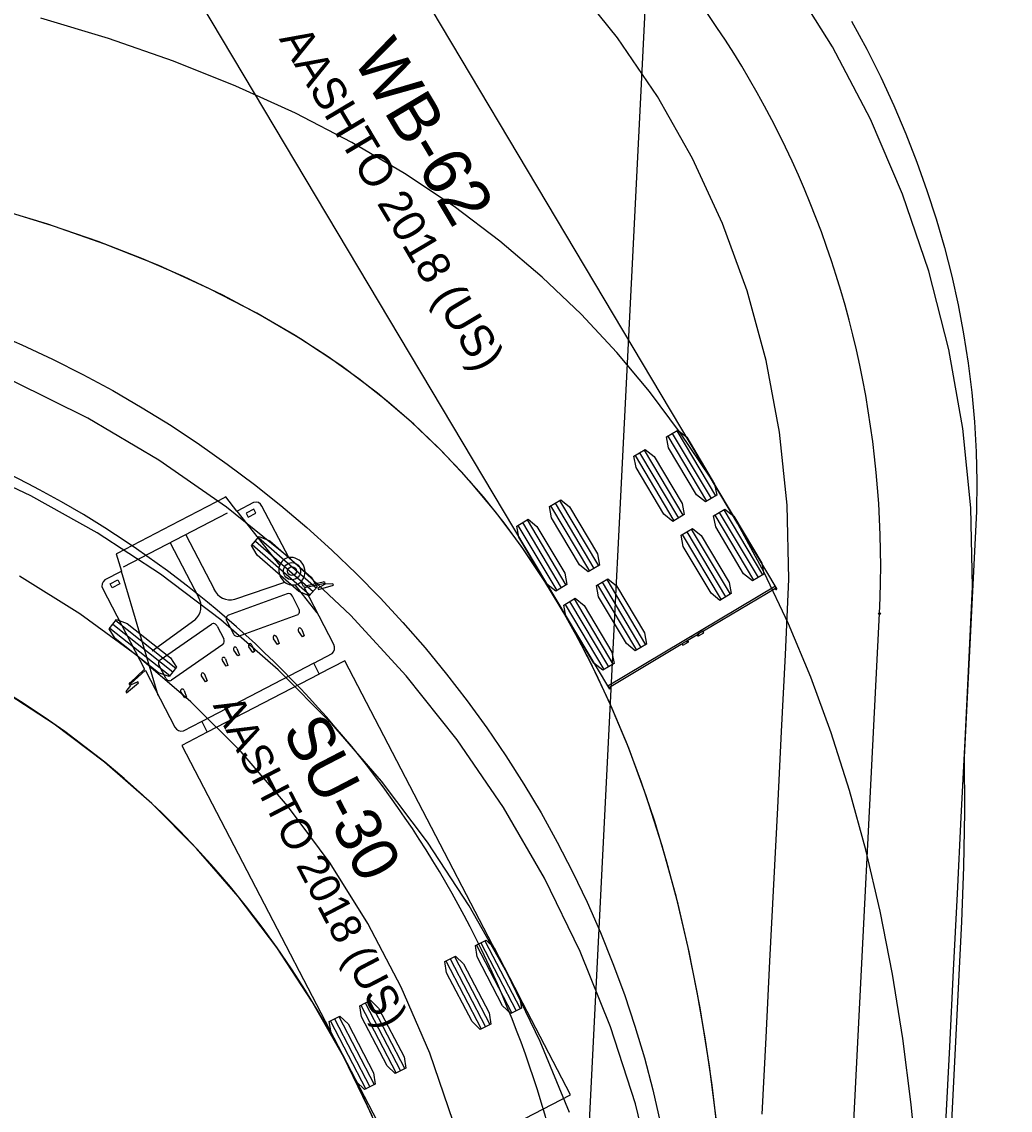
# Model space of a CAD drawing. Extents: x 260275 to 261282, y 610916 to 614143.
# Drawn here: x 261043.72 to 261086.74, y 612552.98 to 612600.34 of the extents above; entities that cross this region are included whole.
import ezdxf

# ---------------------------------------------------------------- set-up
doc = ezdxf.new("R2010")
doc.units = 0
doc.layers.add('GE_X_Alignment', color=7, linetype='Continuous')
doc.layers.add('TopoDOT_Transients', color=7, linetype='Continuous')

msp = doc.modelspace()

# ---------------------------------------------------------------- linework, layer by layer
at = {"layer": 'GE_X_Alignment'}
msp.add_line((260986.249, 610915.954), (261148.276, 614142.838), dxfattribs=at)
at = {"layer": 'TopoDOT_Transients'}
for p, q in [((261072.027, 612582.431), (261073.717, 612579.596)), ((261072.224, 612582.548), (261073.914, 612579.713)), ((261071.831, 612582.313), (261073.52, 612579.478)), ((261070.61, 612581.586), (261072.299, 612578.751)), ((261070.807, 612581.703), (261072.496, 612578.868)), ((261070.413, 612581.469), (261072.102, 612578.634)), ((261053.823, 612579.132), (261053.487, 612578.957)), ((261053.913, 612578.96), (261053.823, 612579.132)), ((261055.339, 612577.03), (261054.175, 612579.268)), ((261066.734, 612579.276), (261068.423, 612576.441)), ((261066.93, 612579.393), (261068.62, 612576.558)), ((261067.127, 612579.51), (261068.817, 612576.676)), ((261074.272, 612579.112), (261075.961, 612576.277)), ((261052.665, 612578.963), (261048.136, 612576.609)), ((261054.95, 612576.698), (261053.091, 612579.046)), ((261053.487, 612578.957), (261053.577, 612578.785)), ((261053.577, 612578.785), (261053.913, 612578.96)), ((261065.71, 612578.666), (261067.399, 612575.831)), ((261073.878, 612578.877), (261075.568, 612576.042)), ((261074.075, 612578.994), (261075.764, 612576.16)), ((261065.316, 612578.431), (261067.006, 612575.596)), ((261065.513, 612578.549), (261067.202, 612575.714)), ((261072.855, 612578.267), (261074.544, 612575.432)), ((261050.858, 612578.024), (261052.089, 612575.657)), ((261053.888, 612577.749), (261056.401, 612575.559)), ((261054.025, 612577.907), (261056.538, 612575.716)), ((261072.461, 612578.032), (261074.15, 612575.198)), ((261072.658, 612578.15), (261074.347, 612575.315)), ((261050.179, 612577.671), (261051.409, 612575.304)), ((261053.751, 612577.592), (261056.264, 612575.402)), ((261049.664, 612571.035), (261048.059, 612576.431)), ((261047.568, 612575.881), (261047.904, 612576.056)), ((261047.658, 612575.709), (261047.568, 612575.881)), ((261047.994, 612575.883), (261047.658, 612575.709)), ((261047.904, 612576.056), (261047.994, 612575.883)), ((261052.992, 612575.217), (261055.171, 612575.958)), ((261056.585, 612574.632), (261055.624, 612575.847)), ((261068.781, 612575.84), (261070.471, 612573.005)), ((261068.978, 612575.957), (261070.667, 612573.122)), ((261069.175, 612576.074), (261070.864, 612573.24)), ((261055.27, 612575.456), (261052.718, 612574.526)), ((261055.783, 612574.8), (261055.498, 612575.347)), ((261076.521, 612575.785), (261069.219, 612571.434)), ((261067.364, 612574.995), (261069.053, 612572.16)), ((261067.561, 612575.112), (261069.25, 612572.278)), ((261067.758, 612575.23), (261069.447, 612572.395)), ((261053.162, 612573.606), (261055.714, 612574.537)), ((261059.045, 612136.423), (261081.046, 612574.591)), ((261047.556, 612573.964), (261050.17, 612571.895)), ((261047.686, 612574.127), (261050.299, 612572.058)), ((261047.815, 612574.29), (261050.429, 612572.221)), ((261051.25, 612574.311), (261049.4, 612572.961)), ((261049.745, 612572.584), (261051.973, 612574.139)), ((261052.228, 612574.043), (261052.512, 612573.496)), ((261052.65, 612574.263), (261052.934, 612573.716)), ((261055.906, 612573.9), (261056.012, 612573.618)), ((261054.851, 612573.251), (261054.68, 612573.501)), ((261054.817, 612573.572), (261054.924, 612573.289)), ((261055.939, 612573.58), (261055.769, 612573.829)), ((261056.012, 612573.618), (261055.939, 612573.58)), ((261072.683, 612573.416), (261073.133, 612573.684)), ((261072.906, 612573.549), (261072.87, 612573.61)), ((261073.363, 612573.821), (261073.134, 612573.685)), ((261052.471, 612573.247), (261050.242, 612571.693)), ((261053.122, 612572.748), (261052.952, 612572.998)), ((261053.089, 612573.069), (261053.196, 612572.786)), ((261053.775, 612572.898), (261053.605, 612573.147)), ((261053.742, 612573.218), (261053.848, 612572.936)), ((261054.924, 612573.289), (261054.851, 612573.251)), ((261072.678, 612573.413), (261072.45, 612573.277)), ((261052.625, 612572.3), (261052.455, 612572.549)), ((261052.592, 612572.62), (261052.698, 612572.338)), ((261053.196, 612572.786), (261053.122, 612572.748)), ((261053.848, 612572.936), (261053.775, 612572.898)), ((261049.988, 612571.788), (261049.703, 612572.335)), ((261056.426, 612572.436), (261051.553, 612569.903)), ((261052.698, 612572.338), (261052.625, 612572.3)), ((261051.718, 612571.623), (261051.54, 612571.884)), ((261051.677, 612571.955), (261051.791, 612571.661)), ((261051.791, 612571.661), (261051.718, 612571.623)), ((261056.671, 612571.964), (261051.798, 612569.431)), ((261050.823, 612570.921), (261050.653, 612571.17)), ((261050.79, 612571.242), (261050.896, 612570.959)), ((261050.896, 612570.959), (261050.823, 612570.921)), ((261063.51, 612560.169), (261065.048, 612557.211)), ((261063.695, 612560.265), (261065.233, 612557.307)), ((261063.88, 612560.361), (261065.417, 612557.403)), ((261062.18, 612559.477), (261063.717, 612556.519)), ((261062.364, 612559.573), (261063.902, 612556.615)), ((261062.549, 612559.669), (261064.086, 612556.712)), ((261058.482, 612557.556), (261060.02, 612554.598)), ((261058.667, 612557.652), (261060.205, 612554.694)), ((261058.852, 612557.748), (261060.389, 612554.79)), ((261057.151, 612556.864), (261058.689, 612553.906)), ((261057.336, 612556.96), (261058.874, 612554.002)), ((261057.521, 612557.056), (261059.058, 612554.098))]:
    msp.add_line(p, q, dxfattribs=at)
for points in [[(261076.538, 612575.713), (261076.557, 612575.725), (261052.021, 612616.898), (261048.37, 612614.722), (261044.72, 612612.547), (261069.255, 612571.373), (261069.275, 612571.385)], [(261075.948, 612552.816), (261076.115, 612556.146), (261076.282, 612559.475), (261076.449, 612562.805), (261076.616, 612566.134), (261076.784, 612569.464), (261076.951, 612572.793), (261077.096, 612576.091), (261077.025, 612579.315), (261076.696, 612582.49), (261076.113, 612585.6), (261075.282, 612588.632), (261074.21, 612591.568), (261072.907, 612594.394), (261071.382, 612597.093), (261069.647, 612599.651), (261067.713, 612602.053)], [(261083.938, 612552.415), (261084.105, 612555.744), (261084.272, 612559.074), (261084.439, 612562.404), (261084.606, 612565.733), (261084.773, 612569.063), (261084.941, 612572.392), (261085.088, 612575.755), (261085.017, 612579.193), (261084.677, 612582.646), (261084.068, 612586.089), (261083.192, 612589.496), (261082.051, 612592.842), (261080.651, 612596.105), (261078.999, 612599.26), (261077.103, 612602.288)], [(261082.717, 612550.298), (261082.431, 612553.229), (261082.066, 612556.101), (261081.616, 612558.908), (261081.08, 612561.647), (261080.456, 612564.313), (261079.744, 612566.9), (261078.943, 612569.405), (261078.054, 612571.821), (261077.081, 612574.146), (261076.024, 612576.375), (261074.887, 612578.504), (261073.674, 612580.529), (261072.39, 612582.446), (261071.038, 612584.254), (261069.616, 612585.959), (261068.065, 612587.621), (261066.372, 612589.238), (261064.53, 612590.802), (261062.534, 612592.304), (261060.384, 612593.737), (261058.08, 612595.093), (261055.63, 612596.365), (261053.041, 612597.545), (261050.324, 612598.629), (261047.492, 612599.613), (261044.559, 612600.497)], [(261079.835, 612600.368), (261080.491, 612599.152), (261081.102, 612597.929), (261081.668, 612596.702), (261082.192, 612595.472), (261082.673, 612594.239), (261083.112, 612593.003), (261083.511, 612591.764), (261083.869, 612590.522), (261084.187, 612589.276), (261084.466, 612588.024), (261084.706, 612586.763), (261084.907, 612585.493), (261085.066, 612584.215), (261085.183, 612582.93), (261085.256, 612581.638), (261085.285, 612580.339), (261085.268, 612579.036), (261084.738, 612568.348), (261084.74, 612565.962), (261084.698, 612563.575), (261084.616, 612561.187), (261082.631, 612521.243), (261060.03, 612071.291)], [(261073.983, 612552.295), (261073.65, 612554.907), (261073.245, 612557.436), (261072.766, 612559.879), (261072.215, 612562.233), (261071.591, 612564.494), (261070.898, 612566.661), (261070.136, 612568.73), (261069.31, 612570.7), (261068.423, 612572.569), (261067.48, 612574.335), (261066.484, 612575.996), (261065.44, 612577.552), (261064.355, 612579.001), (261063.225, 612580.354), (261062.002, 612581.663), (261060.666, 612582.938), (261059.203, 612584.177), (261057.601, 612585.382), (261055.851, 612586.547), (261053.949, 612587.665), (261051.893, 612588.73), (261049.688, 612589.734), (261047.34, 612590.67), (261044.857, 612591.532), (261042.252, 612592.316)], [(261074.018, 612551.977), (261073.764, 612554.08), (261073.465, 612556.13), (261073.118, 612558.126), (261072.725, 612560.067), (261072.286, 612561.95), (261071.8, 612563.775), (261071.269, 612565.54), (261070.693, 612567.244), (261070.075, 612568.885), (261069.416, 612570.462), (261068.717, 612571.975), (261067.981, 612573.422), (261067.21, 612574.803), (261066.407, 612576.117), (261065.573, 612577.363), (261064.71, 612578.545), (261063.81, 612579.672), (261062.865, 612580.756), (261061.861, 612581.805), (261060.787, 612582.828), (261059.631, 612583.83), (261058.389, 612584.808), (261057.055, 612585.761), (261055.626, 612586.686), (261054.101, 612587.581), (261052.478, 612588.441), (261050.76, 612589.262), (261048.949, 612590.042), (261047.049, 612590.777), (261045.064, 612591.464), (261043, 612592.102)], [(261042.375, 612586.868), (261043.725, 612586.285), (261045.06, 612585.662), (261046.379, 612584.998), (261047.68, 612584.295), (261048.961, 612583.552), (261050.22, 612582.771), (261051.454, 612581.953), (261052.663, 612581.1), (261053.845, 612580.212), (261054.998, 612579.29), (261056.122, 612578.336), (261057.217, 612577.348), (261058.281, 612576.33), (261059.313, 612575.281), (261060.312, 612574.202), (261061.278, 612573.096), (261062.209, 612571.962), (261063.105, 612570.801), (261063.965, 612569.616), (261064.788, 612568.406), (261065.573, 612567.174), (261066.319, 612565.92), (261067.026, 612564.646), (261067.693, 612563.353), (261068.32, 612562.041), (261068.905, 612560.713), (261069.447, 612559.37), (261069.947, 612558.013), (261070.403, 612556.642), (261070.815, 612555.261), (261071.183, 612553.869), (261071.505, 612552.469)], [(261071.256, 612549.86), (261070.426, 612553.264), (261069.349, 612556.615), (261068.029, 612559.894), (261066.472, 612563.079), (261064.684, 612566.153), (261062.674, 612569.095), (261060.452, 612571.889), (261058.03, 612574.519), (261055.418, 612576.968), (261052.632, 612579.223), (261049.686, 612581.27), (261046.595, 612583.097), (261043.377, 612584.693)], [(261058.969, 612552.742), (261057.735, 612555.289), (261056.351, 612557.734), (261054.819, 612560.07), (261053.144, 612562.287), (261051.331, 612564.376), (261049.387, 612566.327), (261047.319, 612568.133), (261045.137, 612569.785), (261042.849, 612571.275), (261040.462, 612572.599), (261037.905, 612573.799), (261035.184, 612574.889), (261032.334, 612575.869), (261029.384, 612576.746), (261026.355, 612577.528), (261023.265, 612578.226), (261020.127, 612578.849), (261016.951, 612579.406), (261013.747, 612579.907), (261010.518, 612580.359), (261007.272, 612580.769), (261004.01, 612581.142), (261000.737, 612581.485)], [(261067.551, 612552.883), (261066.286, 612555.977), (261064.834, 612558.978), (261063.196, 612561.875), (261061.376, 612564.653), (261059.379, 612567.299), (261057.21, 612569.801), (261054.878, 612572.145), (261052.392, 612574.319), (261049.763, 612576.312), (261047.002, 612578.113), (261044.12, 612579.713), (261041.106, 612581.131)], [(261053.811, 612579.42), (261053.094, 612579.048), (261053.088, 612579.05), (261052.6, 612579.666), (261052.562, 612579.648), (261050.216, 612578.429), (261047.87, 612577.21), (261047.834, 612577.188), (261048.058, 612576.436), (261048.056, 612576.429), (261047.339, 612576.057)], [(261062.499, 612552.496), (261061.479, 612555.469), (261060.24, 612558.343), (261058.789, 612561.104), (261057.137, 612563.739), (261055.294, 612566.235), (261053.271, 612568.579), (261051.08, 612570.759), (261048.734, 612572.766), (261046.246, 612574.588), (261043.631, 612576.217)], [(261056.844, 612575.954), (261056.843, 612575.954), (261056.001, 612575.771), (261055.989, 612575.778), (261055.884, 612575.981)], [(261057.305, 612573.248), (261056.025, 612575.709), (261056.024, 612575.722), (261056.85, 612575.904), (261056.851, 612575.904)], [(261056.87, 612575.891), (261056.891, 612575.852), (261056.891, 612575.852), (261056.613, 612575.698), (261056.611, 612575.696), (261056.636, 612575.647), (261056.64, 612575.648), (261057.286, 612575.826), (261057.288, 612575.828), (261057.258, 612575.885), (261056.936, 612575.866), (261056.936, 612575.866), (261056.913, 612575.908)], [(261047.254, 612575.671), (261049.068, 612572.181), (261049.068, 612572.168), (261048.434, 612571.583), (261048.433, 612571.583)], [(261073.169, 612573.623), (261073.398, 612573.76), (261073.398, 612573.761), (261073.363, 612573.821), (261073.393, 612573.839), (261076.516, 612575.7), (261076.517, 612575.701)], [(261069.295, 612571.397), (261069.296, 612571.398), (261072.419, 612573.259), (261072.45, 612573.277), (261072.486, 612573.217), (261072.487, 612573.217), (261072.716, 612573.354)], [(261050.755, 612569.488), (261051.55, 612569.901), (261051.555, 612569.899), (261051.798, 612569.432), (261051.788, 612569.426), (261050.685, 612568.853), (261060.502, 612549.965), (261064.052, 612551.81), (261067.601, 612553.654), (261057.784, 612572.542), (261056.681, 612571.969), (261056.671, 612571.965), (261056.428, 612572.432), (261056.429, 612572.437), (261057.224, 612572.85)], [(261048.47, 612571.548), (261048.471, 612571.549), (261049.094, 612572.12), (261049.104, 612572.112), (261050.383, 612569.65)], [(261048.431, 612571.499), (261048.452, 612571.457), (261048.452, 612571.457), (261048.251, 612571.204), (261048.281, 612571.146), (261048.284, 612571.148), (261048.802, 612571.574), (261048.804, 612571.576), (261048.778, 612571.625), (261048.776, 612571.624), (261048.49, 612571.486), (261048.49, 612571.486), (261048.47, 612571.525)], [(261059.207, 612552.197), (261058.745, 612553.236), (261058.258, 612554.259), (261057.747, 612555.267), (261057.211, 612556.258), (261056.652, 612557.233), (261056.069, 612558.191), (261055.462, 612559.131), (261054.832, 612560.052), (261054.179, 612560.954), (261053.503, 612561.836), (261052.806, 612562.699), (261052.086, 612563.54), (261051.345, 612564.36), (261050.583, 612565.159), (261049.8, 612565.934), (261048.997, 612566.687), (261048.175, 612567.416), (261047.334, 612568.121), (261046.474, 612568.801), (261045.597, 612569.456), (261044.702, 612570.086), (261043.789, 612570.691), (261042.855, 612571.271)]]:
    msp.add_lwpolyline(points, dxfattribs=at)
for points in [[(261071.782, 612582.284), (261072.273, 612582.577), (261072.658, 612582.268), (261073.874, 612580.227), (261073.962, 612579.742), (261073.471, 612579.449), (261073.086, 612579.758), (261071.87, 612581.799)], [(261070.364, 612581.439), (261070.856, 612581.732), (261071.24, 612581.424), (261072.457, 612579.383), (261072.545, 612578.897), (261072.054, 612578.605), (261071.669, 612578.913), (261070.453, 612580.954)], [(261066.685, 612579.247), (261067.176, 612579.54), (261067.561, 612579.231), (261068.777, 612577.19), (261068.865, 612576.705), (261068.374, 612576.412), (261067.99, 612576.721), (261066.773, 612578.762)], [(261073.829, 612578.848), (261074.321, 612579.141), (261074.705, 612578.832), (261075.922, 612576.791), (261076.01, 612576.306), (261075.519, 612576.013), (261075.134, 612576.322), (261073.918, 612578.363)], [(261065.267, 612578.402), (261065.759, 612578.695), (261066.143, 612578.386), (261067.36, 612576.345), (261067.448, 612575.86), (261066.957, 612575.567), (261066.572, 612575.876), (261065.356, 612577.917)], [(261072.412, 612578.003), (261072.903, 612578.296), (261073.288, 612577.987), (261074.504, 612575.946), (261074.593, 612575.461), (261074.101, 612575.168), (261073.717, 612575.477), (261072.5, 612577.518)], [(261053.717, 612577.554), (261054.059, 612577.945), (261054.514, 612577.757), (261056.323, 612576.18), (261056.572, 612575.755), (261056.23, 612575.363), (261055.775, 612575.551), (261053.966, 612577.129)], [(261068.732, 612575.811), (261069.224, 612576.103), (261069.608, 612575.795), (261070.825, 612573.754), (261070.913, 612573.269), (261070.422, 612572.976), (261070.037, 612573.284), (261068.821, 612575.326)], [(261067.315, 612574.966), (261067.806, 612575.259), (261068.191, 612574.95), (261069.407, 612572.909), (261069.496, 612572.424), (261069.004, 612572.131), (261068.62, 612572.44), (261067.403, 612574.481)], [(261047.524, 612573.923), (261047.847, 612574.331), (261048.31, 612574.164), (261050.192, 612572.674), (261050.461, 612572.262), (261050.138, 612571.854), (261049.675, 612572.021), (261047.793, 612573.511)], [(261063.465, 612560.145), (261063.926, 612560.385), (261064.28, 612560.043), (261065.387, 612557.913), (261065.463, 612557.427), (261065.002, 612557.187), (261064.648, 612557.529), (261063.541, 612559.659)], [(261062.134, 612559.453), (261062.595, 612559.693), (261062.949, 612559.351), (261064.056, 612557.222), (261064.132, 612556.735), (261063.671, 612556.496), (261063.317, 612556.837), (261062.21, 612558.967)], [(261058.437, 612557.532), (261058.898, 612557.772), (261059.252, 612557.43), (261060.359, 612555.3), (261060.435, 612554.814), (261059.974, 612554.574), (261059.62, 612554.916), (261058.513, 612557.045)], [(261057.106, 612556.84), (261057.567, 612557.08), (261057.921, 612556.738), (261059.028, 612554.608), (261059.104, 612554.122), (261058.643, 612553.882), (261058.289, 612554.224), (261057.182, 612556.354)]]:
    msp.add_lwpolyline(points, close=True, dxfattribs=at)
for centre, radius in [((261055.482, 612576.439), 0.374), ((261055.482, 612576.439), 0.193), ((261076.545, 612575.678), 0.0266), ((261081.046, 612574.591), 0.0417), ((261081.046, 612574.591), 0.0417), ((261069.302, 612571.362), 0.0266)]:
    msp.add_circle(centre, radius, dxfattribs=at)
for centre, radius, start, end in [((261039.099, 612576.697), 42, 357.1255, 114.9182), ((261023.254, 612540.309), 45, 357.1255, 87.1346), ((261053.916, 612579.159), 0.282, 22.8353, 111.9147), ((261055.443, 612576.515), 0.526, 101.4083, 159.6543), ((261055.423, 612576.408), 0.628, 317.2164, 97.7081), ((261055.539, 612576.477), 0.629, 159.5087, 208.198), ((261047.493, 612575.821), 0.282, 123.0115, 212.0909), ((261055.547, 612576.464), 0.63, 206.8179, 259.2207), ((261055.523, 612576.361), 0.524, 259.7221, 313.5222), ((261056.878, 612575.93), 0.0418, 327.9562, 144.9712), ((261056.883, 612575.933), 0.0434, 221.3766, 252.0494), ((261052.797, 612575.965), 0.773, 203.4885, 284.5726), ((261055.321, 612575.271), 0.193, 23.4062, 105.3207), ((261076.545, 612575.678), 0.0363, 140.552, 101.7146), ((261050.75, 612574.9), 0.773, 310.3536, 31.4377), ((261052.804, 612574.363), 0.184, 118.0612, 212.9214), ((261055.628, 612574.7), 0.184, 298.0557, 32.9269), ((261052.057, 612573.974), 0.184, 22.0048, 116.865), ((261055.839, 612573.887), 0.0909, 124.947, 219.1822), ((261055.818, 612573.876), 0.091, 15.7796, 109.9435), ((261052.348, 612573.396), 0.193, 309.6006, 31.5249), ((261053.111, 612573.792), 0.193, 203.4012, 285.3256), ((261054.751, 612573.558), 0.0909, 124.947, 219.1822), ((261054.73, 612573.547), 0.091, 15.7796, 109.9435), ((261073.151, 612573.654), 0.0352, 120.1893, 300.7758), ((261073.151, 612573.654), 0.0354, 305.0829, 117.2684), ((261053.023, 612573.055), 0.091, 124.9827, 219.1465), ((261053.002, 612573.044), 0.091, 15.7796, 109.9435), ((261053.675, 612573.205), 0.0909, 124.947, 219.1822), ((261053.654, 612573.194), 0.091, 15.7796, 109.9435), ((261057.018, 612573.099), 0.323, 309.6147, 27.4631), ((261072.698, 612573.384), 0.0352, 120.5789, 303.2183), ((261072.698, 612573.384), 0.0352, 300.807, 121.3935), ((261049.868, 612572.436), 0.193, 129.6055, 211.52), ((261052.525, 612572.607), 0.091, 124.9827, 219.1465), ((261052.504, 612572.596), 0.0909, 15.744, 109.9792), ((261051.618, 612571.93), 0.091, 124.9827, 219.1465), ((261051.597, 612571.919), 0.0909, 15.744, 109.9792), ((261048.433, 612571.541), 0.0418, 89.955, 266.9699), ((261048.428, 612571.538), 0.0434, 342.8768, 13.5496), ((261050.159, 612571.857), 0.184, 201.9993, 296.8705), ((261050.724, 612571.228), 0.091, 124.9827, 219.1465), ((261050.703, 612571.217), 0.0909, 15.744, 109.9792), ((261069.302, 612571.361), 0.0363, 139.8682, 101.0308), ((261050.67, 612569.799), 0.323, 207.4631, 285.3115)]:
    msp.add_arc(centre, radius, start, end, dxfattribs=at)

# ---------------------------------------------------------------- texts
for s, height, rotation, p in [('AASHTO 2018 (US)', 1.41667, 300.7914, (261054.901, 612599.598)), ('WB-62', 2.125, 300.7914, (261058.083, 612598.756)), ('AASHTO 2018 (US)', 1.33333, 297.4631, (261052.026, 612570.595)), ('SU-30', 2, 297.4631, (261055.036, 612569.503))]:
    msp.add_text(s, height=height, rotation=rotation, dxfattribs=at).set_placement(p)

doc.saveas('drawing.dxf')
